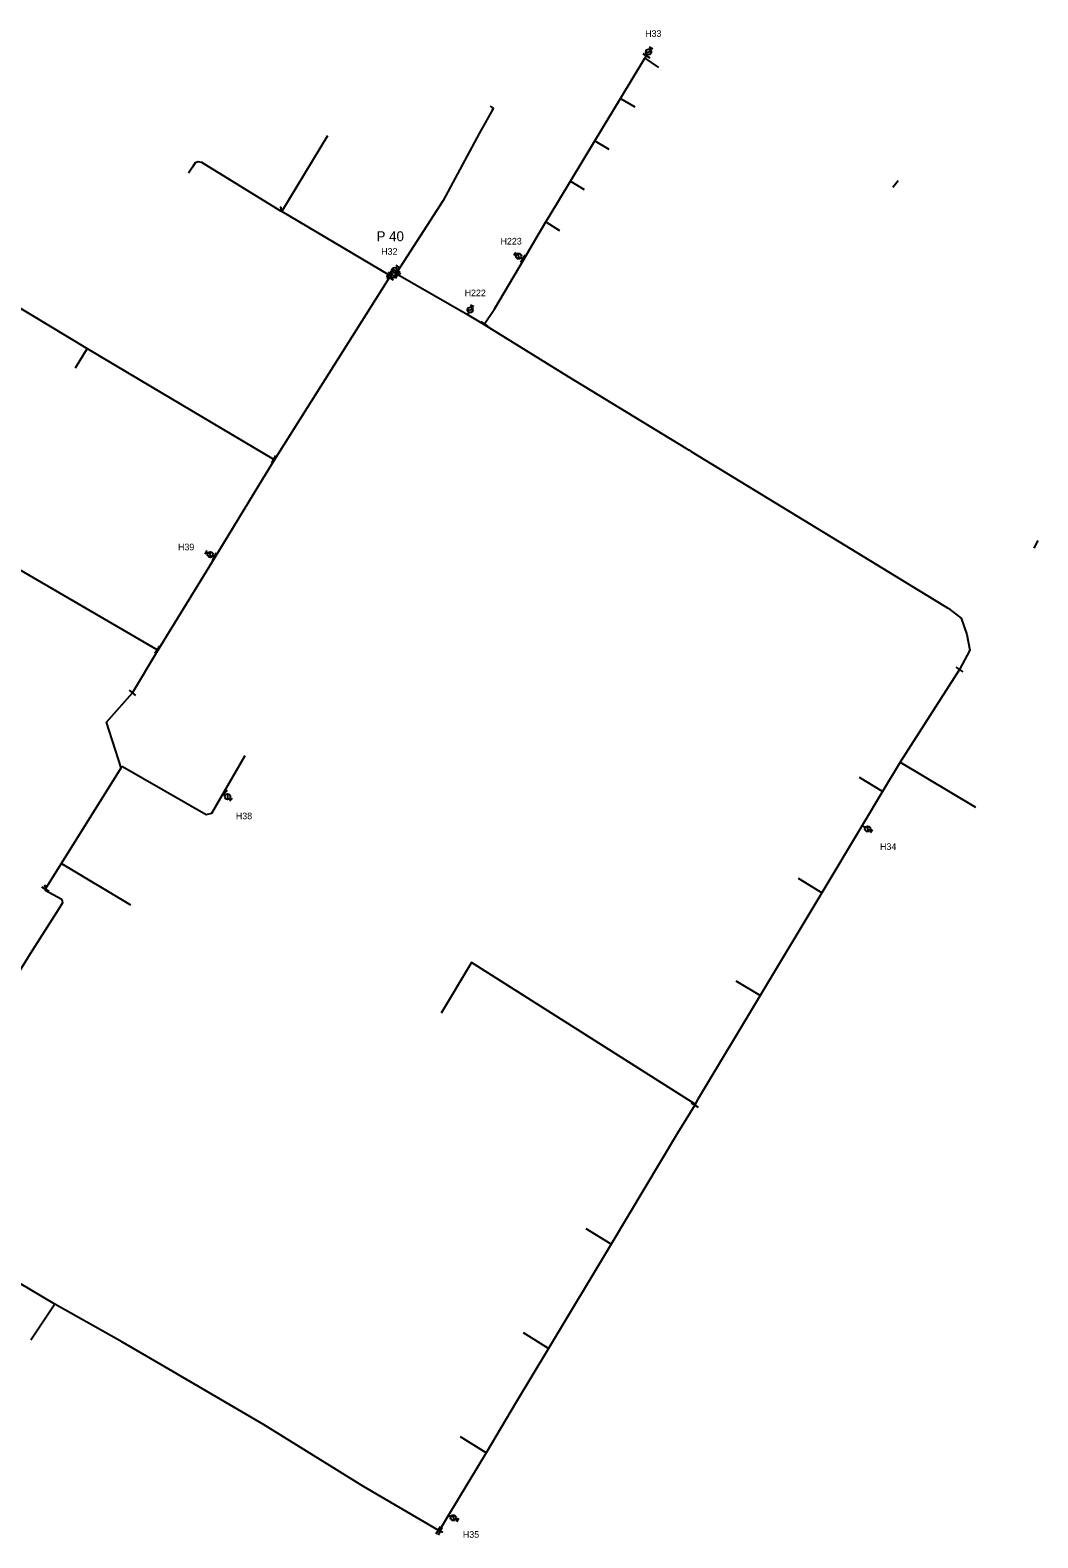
# Model space of a CAD drawing. Extents: x -548873 to -538270, y -1201997 to -1192514.
# Drawn here: x -543885.3 to -543581.1, y -1193736.5 to -1193281.2 of the extents above; entities that cross this region are included whole.
import ezdxf

# ---------------------------------------------------------------- set-up
doc = ezdxf.new("R2010")
doc.units = 0
for name, color, linetype in [('KN_HRAN_STÁTNÍ', 7, 'Continuous'), ('KN_PARC_Č', 7, 'Continuous'), ('KN_VKP_HRAN_SPORNÁ', 7, 'Continuous'), ('PK_PARC_Čv', 7, 'Continuous'), ('Vrstva 29', 7, 'Continuous'), ('Vrstva 39', 7, 'Continuous')]:
    doc.layers.add(name, color=color, linetype=linetype)

# ---------------------------------------------------------------- blocks, each defined once
blk = doc.blocks.new('160')
at = {"layer": 'KN_HRAN_STÁTNÍ'}
blk.add_circle((0, 0), 0.0458, dxfattribs=at)
blk = doc.blocks.new('147')
at = {"layer": 'KN_HRAN_STÁTNÍ'}
blk.add_line((0, 1.27), (0, -1.27), dxfattribs=at)
blk = doc.blocks.new('133')
at = {"layer": 'KN_HRAN_STÁTNÍ'}
for p, q in [((0.28, 0), (0, 0)), ((0.54, 0.58), (1.7, -0.58)), ((1.94, 0), (2.52, 0)), ((2.52, 0.58), (2.52, -0.58))]:
    blk.add_line(p, q, dxfattribs=at)
blk.add_circle((1.11, 0), 0.825, dxfattribs=at)
blk = doc.blocks.new('150')
at = {"layer": 'KN_HRAN_STÁTNÍ'}
blk.add_line((0, 1.27), (0, -1.27), dxfattribs=at)
blk = doc.blocks.new('124')
at = {"layer": 'KN_HRAN_STÁTNÍ'}
for q in [(-0.19, 1.22), (-0.19, 0.92), (0.19, 1.22), (0, 0), (0.19, 0.92)]:
    blk.add_line((0, 1.07), q, dxfattribs=at)
blk = doc.blocks.new('128')
at = {"layer": 'KN_HRAN_STÁTNÍ'}
for p, q in [((-0.19, 1.06), (-0.43, 1.15)), ((-0.36, 0.84), (-0.19, 1.06)), ((-0.19, 1.06), (-0.02, 1.25)), ((-0.19, 1.06), (0, 0)), ((0.05, 0.95), (-0.19, 1.06)), ((-0.1, 1), (0.41, 0.91)), ((-0.07, 0.82), (0.17, 0.96)), ((0.17, 0.96), (-0.02, 1.13)), ((0.17, 0.96), (0, 0)), ((0.19, 1.21), (0.17, 0.96)), ((0.17, 0.96), (0.38, 1.08)), ((0.36, 0.77), (0.17, 0.96))]:
    blk.add_line(p, q, dxfattribs=at)

msp = doc.modelspace()

# ---------------------------------------------------------------- linework, layer by layer
at = {"layer": 'KN_PARC_Č'}
for points in [[(-543699.777, -1193289.693), (-543695.565, -1193292.484)], [(-543745.703, -1193305.23), (-543745.423, -1193304.73), (-543746.37, -1193304.153), (-543746.371, -1193304.153)], [(-543707.097, -1193301.819), (-543702.794, -1193304.342)], [(-543809.341, -1193335.991), (-543795.479, -1193313.022)], [(-543714.837, -1193314.643), (-543710.593, -1193317.191)], [(-543836.28, -1193322.582), (-543837.478, -1193324.362)], [(-543722.18, -1193326.808), (-543718.056, -1193329.348)], [(-543729.603, -1193339.109), (-543725.547, -1193341.718)], [(-543868.035, -1193377.358), (-543871.723, -1193383.246)], [(-543857.954, -1193503.675), (-543857.371, -1193503.532), (-543832.194, -1193518.04), (-543830.468, -1193517.612), (-543820.377, -1193500.227)], [(-543622.681, -1193502.265), (-543599.939, -1193515.861)], [(-543627.969, -1193511.073), (-543634.922, -1193506.912)], [(-543600.21, -1193515.699), (-543599.885, -1193515.557)], [(-543875.815, -1193532.834), (-543855.034, -1193545.317)], [(-543646.323, -1193541.697), (-543653.347, -1193537.367)], [(-543684.534, -1193605.511), (-543752.038, -1193562.772), (-543761.236, -1193578.087)], [(-543664.944, -1193572.765), (-543672.188, -1193568.411)], [(-543709.929, -1193647.821), (-543717.455, -1193643.221)], [(-543877.87, -1193665.94), (-543885.095, -1193676.778)], [(-543728.82, -1193679.34), (-543736.415, -1193674.605)], [(-543747.668, -1193710.787), (-543755.415, -1193706.036)]]:
    msp.add_lwpolyline(points, dxfattribs=at)
at = {"layer": 'KN_VKP_HRAN_SPORNÁ'}
for points in [[(-543748.1, -1193369.884), (-543745.02, -1193365.25), (-543736.278, -1193350.427), (-543733.63, -1193345.937), (-543729.603, -1193339.109), (-543728.64, -1193337.511), (-543722.18, -1193326.808), (-543714.837, -1193314.643), (-543707.097, -1193301.819), (-543699.777, -1193289.692), (-543699.697, -1193289.561), (-543699.384, -1193289.041)], [(-543745.703, -1193305.23), (-543746.099, -1193305.939), (-543749.74, -1193312.46), (-543760.66, -1193332.7), (-543774.52, -1193354.23)], [(-543809.597, -1193335.834), (-543833.5, -1193321.17), (-543834.59, -1193321), (-543835.43, -1193321.32), (-543836.28, -1193322.582)], [(-543946.94, -1193330.374), (-543929.309, -1193341.278), (-543896.896, -1193360.029), (-543868.044, -1193377.352), (-543852.169, -1193386.784), (-543811.82, -1193410.76)], [(-543776.996, -1193355.163), (-543777.212, -1193355.035), (-543809.341, -1193335.991), (-543809.597, -1193335.834)], [(-543776.493, -1193355.461), (-543776.996, -1193355.163)], [(-543776.782, -1193355.928), (-543776.493, -1193355.461)], [(-543776.493, -1193355.461), (-543775.627, -1193355.971), (-543774.811, -1193354.683)], [(-543774.52, -1193354.23), (-543774.811, -1193354.683)], [(-543774.811, -1193354.683), (-543774.335, -1193354.956)], [(-543774.335, -1193354.956), (-543753.24, -1193367.08), (-543748.23, -1193370.08)], [(-543811.511, -1193410.943), (-543776.782, -1193355.928)], [(-543748.23, -1193370.08), (-543748.1, -1193369.884)], [(-543748.23, -1193370.08), (-543722.9, -1193385.83), (-543687.33, -1193407.48), (-543686.48, -1193407.97)], [(-543686.48, -1193407.97), (-543685.73, -1193408.46), (-543639.36, -1193436.7), (-543609.39, -1193455.02), (-543608.593, -1193455.537)], [(-543846.712, -1193468.518), (-543829.467, -1193440.312), (-543815.05, -1193416.732), (-543811.511, -1193410.943)], [(-543811.82, -1193410.76), (-543811.511, -1193410.943)], [(-543846.949, -1193468.336), (-543900.323, -1193437.374), (-543902.155, -1193440.314)], [(-543608.593, -1193455.537), (-543608.19, -1193455.8), (-543604.21, -1193458.75), (-543602.51, -1193463.66), (-543601.68, -1193468.4), (-543604.713, -1193474.295)], [(-543854.359, -1193481.329), (-543846.712, -1193468.518)], [(-543846.712, -1193468.518), (-543846.949, -1193468.336)], [(-543604.713, -1193474.295), (-543622.681, -1193502.265), (-543627.969, -1193511.073), (-543634.131, -1193521.354), (-543646.323, -1193541.697), (-543664.944, -1193572.765), (-543683.814, -1193604.24), (-543684.556, -1193605.55), (-543684.69, -1193605.791)], [(-543880.646, -1193540.672), (-543879.72, -1193539.11), (-543857.859, -1193503.975), (-543862.235, -1193490.194), (-543854.359, -1193481.329)], [(-543880.646, -1193540.672), (-543880.8, -1193540.93), (-543875.93, -1193543.5), (-543875.59, -1193544.16), (-543875.52, -1193544.73), (-543876.666, -1193546.543), (-543885.28, -1193560.17), (-543896.15, -1193577.68), (-543898.43, -1193581.45), (-543918.217, -1193612.891), (-543920.57, -1193616.63), (-543921.12, -1193616.76), (-543923.31, -1193615.49), (-543925.61, -1193614.27), (-543925.64, -1193614.26), (-543925.93, -1193614.67), (-543926.307, -1193615.365)], [(-543684.69, -1193605.791), (-543689.836, -1193614.297), (-543709.929, -1193647.821), (-543728.82, -1193679.34), (-543738.548, -1193695.572), (-543747.668, -1193710.787), (-543758.976, -1193729.654), (-543761.806, -1193734.376)], [(-543762.09, -1193734.21), (-543784.71, -1193720.96), (-543814.88, -1193702.29), (-543844.6, -1193684.81), (-543857.621, -1193677.349), (-543877.87, -1193665.94), (-543902.98, -1193651.06), (-543916.87, -1193642.83), (-543937.5, -1193632.88), (-543927.199, -1193616.855)], [(-543761.806, -1193734.376), (-543762.09, -1193734.21)], [(-543761.806, -1193734.376), (-543761.47, -1193734.52)], [(-543761.47, -1193734.52), (-543760.985, -1193734.728)]]:
    msp.add_lwpolyline(points, dxfattribs=at)
at = {"layer": 'PK_PARC_Čv'}
for points in [[(-543699.384, -1193289.041), (-543699.3, -1193288.902), (-543699.19, -1193288.72)], [(-543736.278, -1193350.427), (-543736.88, -1193350.05)], [(-543776.493, -1193355.461), (-543775.89, -1193354.62)], [(-543753.24, -1193367.08), (-543753.01, -1193366.66)], [(-543829.467, -1193440.312), (-543829.705, -1193440.193), (-543829.905, -1193440.093)], [(-543826.92, -1193511.5), (-543826.5, -1193511.906)], [(-543634.131, -1193521.354), (-543633.422, -1193521.81)], [(-543758.976, -1193729.654), (-543758.52, -1193729.91)]]:
    msp.add_lwpolyline(points, dxfattribs=at)

# ---------------------------------------------------------------- block references
for name, p, xscale, yscale, rotation in [('133', (-543699.19, -1193288.72), 1.0000000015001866, 1.0000000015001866, 59.00000017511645), ('150', (-543699.3, -1193288.902), 1.0000000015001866, 1.0000000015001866, 59.00000017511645), ('150', (-543624.066, -1193327.693), 1.000000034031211, 1.0000000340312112, -38.000000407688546), ('133', (-543736.88, -1193350.05), 0.9999999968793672, 0.9999999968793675, 147.99999972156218), ('150', (-543736.56, -1193350.25), 0.9999999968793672, 0.9999999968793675, -32.00000027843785), ('150', (-543776.156, -1193354.991), 1.000000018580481, 1.000000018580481, 54.99999976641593), ('133', (-543775.89, -1193354.62), 1.000000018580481, 1.000000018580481, 54.99999976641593), ('133', (-543753.01, -1193366.66), 0.9999999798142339, 0.9999999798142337, 61.99999866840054), ('150', (-543581.69, -1193436.48), 1.0169562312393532, 1.016956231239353, -26.97601645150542), ('133', (-543829.905, -1193440.093), 1.0138865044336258, 1.0138865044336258, 152.43468640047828), ('150', (-543829.705, -1193440.193), 1.0138865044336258, 1.0138865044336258, -27.56531359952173), ('150', (-543826.681, -1193511.731), 1.0000000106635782, 1.0000000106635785, -44.00000165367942), ('133', (-543826.5, -1193511.906), 1.0000000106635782, 1.0000000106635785, -44.00000165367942), ('133', (-543633.422, -1193521.81), 0.9999999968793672, 0.9999999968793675, -32.00000027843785), ('133', (-543758.52, -1193729.91), 1.0037042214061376, 1.0037042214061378, -29.379208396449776)]:
    msp.add_blockref(name, p, dxfattribs=dict(at, xscale=xscale, yscale=yscale, rotation=rotation))
at = {"layer": 'Vrstva 29'}
for name, p, xscale, yscale, rotation in [('160', (-543699.384, -1193289.041), 1.0000000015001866, 1.0000000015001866, -120.99999982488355), ('160', (-543745.703, -1193305.23), 1.0000000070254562, 1.0000000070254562, -118.99999892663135), ('160', (-543836.28, -1193322.582), 0.9999999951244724, 0.9999999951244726, -123.00000127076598), ('160', (-543809.597, -1193335.834), 1.0000000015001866, 1.0000000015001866, 149.00000017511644), ('147', (-543776.782, -1193355.928), 1.0000000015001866, 1.0000000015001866, 59.00000017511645), ('147', (-543776.996, -1193355.163), 0.9999999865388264, 0.9999999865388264, -30.00000044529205), ('160', (-543776.493, -1193355.461), 1.0009848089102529, 1.000984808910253, 14.224326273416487), ('147', (-543774.52, -1193354.23), 0.9999999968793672, 0.9999999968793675, -122.00000027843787), ('147', (-543774.335, -1193354.956), 1.0037042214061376, 1.0037042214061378, 150.62079160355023), ('160', (-543774.811, -1193354.683), 0.9999999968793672, 0.9999999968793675, 57.99999972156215), ('147', (-543748.1, -1193369.884), 0.9999999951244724, 0.9999999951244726, -123.00000127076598), ('160', (-543748.23, -1193370.08), 0.9999999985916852, 0.9999999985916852, -76.99999972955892), ('147', (-543811.82, -1193410.76), 0.9999999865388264, 0.9999999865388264, -30.00000044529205), ('160', (-543686.48, -1193407.97), 1.0000000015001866, 1.0000000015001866, -30.99999982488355), ('160', (-543811.511, -1193410.943), 1.0000000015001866, 1.0000000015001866, 59.00000017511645), ('160', (-543608.593, -1193455.537), 0.9999999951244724, 0.9999999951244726, -33.000001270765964), ('147', (-543846.949, -1193468.336), 0.9999999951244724, 0.9999999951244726, -33.000001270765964), ('160', (-543846.712, -1193468.518), 1.0060666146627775, 1.0060666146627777, -167.3452647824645), ('147', (-543604.713, -1193474.295), 0.9999999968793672, 0.9999999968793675, -122.00000027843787), ('147', (-543854.359, -1193481.329), 1.0000000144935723, 1.0000000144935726, -130.99999910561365), ('147', (-543880.646, -1193540.672), 0.9999999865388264, 0.9999999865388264, -120.00000044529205), ('147', (-543684.69, -1193605.791), 0.9999999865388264, 0.9999999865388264, 59.99999955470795), ('147', (-543762.09, -1193734.21), 0.9999999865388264, 0.9999999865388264, 149.99999955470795), ('147', (-543761.47, -1193734.52), 1.0225848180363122, 1.0225848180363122, 154.18102564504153), ('160', (-543761.806, -1193734.376), 1.0138865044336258, 1.0138865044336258, -27.56531359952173), ('160', (-543760.985, -1193734.728), 1.0225848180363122, 1.0225848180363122, -25.81897435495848)]:
    msp.add_blockref(name, p, dxfattribs=dict(at, xscale=xscale, yscale=yscale, rotation=rotation))
at = {"layer": 'Vrstva 39'}
for name, p in [('124', (-543809.597, -1193335.834)), ('128', (-543880.646, -1193540.672))]:
    msp.add_blockref(name, p, dxfattribs=at)

# ---------------------------------------------------------------- texts
at = {"layer": 'PK_PARC_Čv'}
for s, height, p in [('H33', 2, (-543699.63, -1193283.24)), ('P 40', 3, (-543780.72, -1193344.95)), ('H223', 2, (-543743.29, -1193345.94)), ('H32', 2, (-543779.31, -1193349.04)), ('H222', 2, (-543754.13, -1193361.55)), ('H39', 2, (-543840.655, -1193438.283)), ('H38', 2, (-543823.19, -1193519.506)), ('H34', 2, (-543628.722, -1193528.77)), ('H35', 2, (-543754.66, -1193736.47))]:
    msp.add_text(s, height=height, dxfattribs=at).set_placement(p)

doc.saveas('drawing.dxf')
